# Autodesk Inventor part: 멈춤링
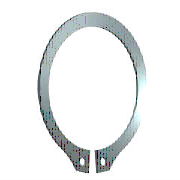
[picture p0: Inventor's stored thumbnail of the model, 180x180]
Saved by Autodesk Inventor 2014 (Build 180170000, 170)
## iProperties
IsCustomPart: 0
Created: 2009-02
Part Number: 멈춤링
Material: 강, 연강
Description: 리테이닝 링(C형)
Document SubType Name: Modeling
Standard: KS B 1336
Designer: KYOUNG IL JANG
Standards Organization: KS
Language: ko-KR
Size Designation: 22 x 1.2
Categories: <MemberInstance><Categories><Category DisplayName="샤프트 부품" InternalName="7f7aeb1f-a693-4053-b835-cee3144e0d98" Mnemonic="SHFT"><Category DisplayName="써클립" Inter
Density: 7.86 g/cm^3
Mass: 1.8286 g
Surface Area: 5.91219 cm^2
Volume: 0.232646 cm^3
Appearance: 강철
Author: KYOUNG IL JANG
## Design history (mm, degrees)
sketch "스케치1"
  geometry: L1 (-6, 0)-(6, 0) reference; L2 (0, 20.189)-(0, -80.536) reference; L3 (-48.09, 0)-(48.09, 0) reference; L4 (-0.5, -21.488)-(-0.5, -25.588); L5 (-0.5, -6.54)-(-0.5, -13.29); L6 (-2.795, 2.7)-(3.672, 2.7); L7 (0.5, -6.54)-(0.5, -13.29); L8 (0.5, -21.488)-(0.5, -25.588); C1 r 1 at (-2, -23.437); C2 r 1 at (2, -23.437); A1 r 10.5 centre (0, -11) between (0.5, -21.488) and (-0.5, -21.488); A2 r 13.025 centre (0, -10.325) between (5.149, -22.289) and (-5.149, -22.289); A3 r 14.597 centre (0, -11) between (-2.318, -25.411) and (-0.5, -25.588); A4 r 2 centre (-2, -23.437) between (-3.97, -23.781) and (-2.318, -25.411); A5 r 2 centre (-5.94, -24.126) between (-3.97, -23.781) and (-5.149, -22.289); A6 r 2 centre (5.94, -24.126) between (5.149, -22.289) and (3.97, -23.781); A7 r 2 centre (2, -23.437) between (2.318, -25.411) and (3.97, -23.781); A8 r 14.597 centre (0, -11) between (0.5, -25.588) and (2.318, -25.411)
  constraints: 16 point on circle, 12 end point, 10 centre point, 9 symmetric about line, 5 point on line, 4 tangent, 3 coincident, 2 horizontal, 1 perpendicular, 1 vertical, 5 other
  dimensions: "d0" = 21 diameter of A1 (= ND); "d1" = 4.1 distance of L4.end L4.start (= SRB2); "d6" = 0.5 distance between parallel lines of L2 L5 (= 0.25 x SD5); "d7" = 2.7 distance between parallel lines of L6 L3 (= SRB1); "d8" = 0.675 distance of A1.centre A2.centre (= 0.25 x SRB1); "d9" = 2 radius of A4 (= SD5); "d10" = 2 radius of A5 (= SD5); "d11" = 1.5 distance from line of L4 A4.centre (= 0.75 x SD5); "d12" = 2 diameter of C1 (= SD5); "d13" = 2 diameter of C2 (= SD5); "d14" = 11 distance from line of A1.centre L1 (= 0.5 x WD)
extrude "본체" new body sketch "스케치1" distance "d2" = 1.2 (= SD); taper "d3" = 0 deg
workaxis "Work Axis1"
workplane "Work Plane1"
body "Solid1"
other parameters: "WD" = 22 (= WDMIN) [user parameter; used in 1 equation term], "SD" = 1.2 [user parameter; used in 1 equation term], "SRB1" = 2.7 [user parameter; used in 2 equation terms], "ND" = 21 [user parameter; used in 1 equation term], "SRB2" = 4.1 [user parameter; used in 1 equation term], "SD5" = 2 [user parameter; used in 6 equation terms], "d15" = 0, "d16" = 0, "d17" = 0, "d41" = 0, "d42" = 0, "WDMIN" = 22 [user parameter; used in 1 equation term], "SD3" = 20.5 [user parameter], "WDMAX" = 24 [user parameter]
